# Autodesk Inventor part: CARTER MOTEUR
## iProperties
Shininess: 64.0
Length Units: 11269
Angle Units: 11279
Time Units: 11290
Mass Units: 11283
Length Display Precision: 3
Angle Display Precision: 2
Compacted: True
Part Number: CARTER MOTEUR
Document SubType Name: Modeling
Created: 2004-08
Material: Par défaut
Designer: Sophie
Density: 1 g/cm^3
Density: 0.0
Volumn: 0.0
Area: 0.0
PropertySet Name: Model Information
Control State: 0
Master: False
Checked Out: False
Author: Sophie
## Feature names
1. Extrusion1
2. Extrusion2
3. Extrusion3
4. Extrusion4
5. Extrusion5
6. Extrusion6
7. Symétrie1 [Mirror]
8. Extrusion7
9. Extrusion8
10. Extrusion9
11. Symétrie2 [Mirror]
12. Extrusion10
13. Extrusion11
14. Extrusion14
15. Congé1 [Fillet]
16. Congé2 [Fillet]
17. Extrusion15
18. Congé3 [Fillet]
19. Perçage1 [Hole]
20. Extrusion16
21. Extrusion17
22. Congé5 [Fillet]
23. Congé6 [Fillet]
24. Extrusion18
25. Extrusion19
26. Extrusion20
27. Extrusion21
28. Extrusion22
29. Extrusion23
30. Symétrie3 [Mirror]
31. Extrusion24
32. Extrusion25
33. Symétrie5 [Mirror]
34. Extrusion26
35. Extrusion27
36. Extrusion28
37. Extrusion29
38. Extrusion30
39. Perçage2 [Hole]
40. Symétrie6 [Mirror]
41. Extrusion31
42. Perçage3 [Hole]
43. Congé7 [Fillet]
44. Congé8 [Fillet]
45. Symétrie7 [Mirror]
46. Congé9 [Fillet]
47. Extrusion32
48. Extrusion33
49. Perçage4 [Hole]
50. Extrusion34
51. Congé10 [Fillet]
52. Symétrie8 [Mirror]
53. Congé11 [Fillet]
54. Perçage5 [Hole]
55. Symétrie9 [Mirror]
56. Congé12 [Fillet]
57. Congé13 [Fillet]
58. Congé14 [Fillet]
59. Congé15 [Fillet]
60. Congé16 [Fillet]
61. Congé17 [Fillet]
62. Congé18 [Fillet]
63. Congé19 [Fillet]
64. Congé20 [Fillet]
65. Congé21 [Fillet]
66. Congé22 [Fillet]
67. Congé23 [Fillet]
68. Congé24 [Fillet]
69. Congé25 [Fillet]
70. Congé26 [Fillet]
71. Congé27 [Fillet]
72. Congé29 [Fillet]
73. Extrusion36
74. Congé30 [Fillet]
75. Congé31 [Fillet]
76. Congé32 [Fillet]
